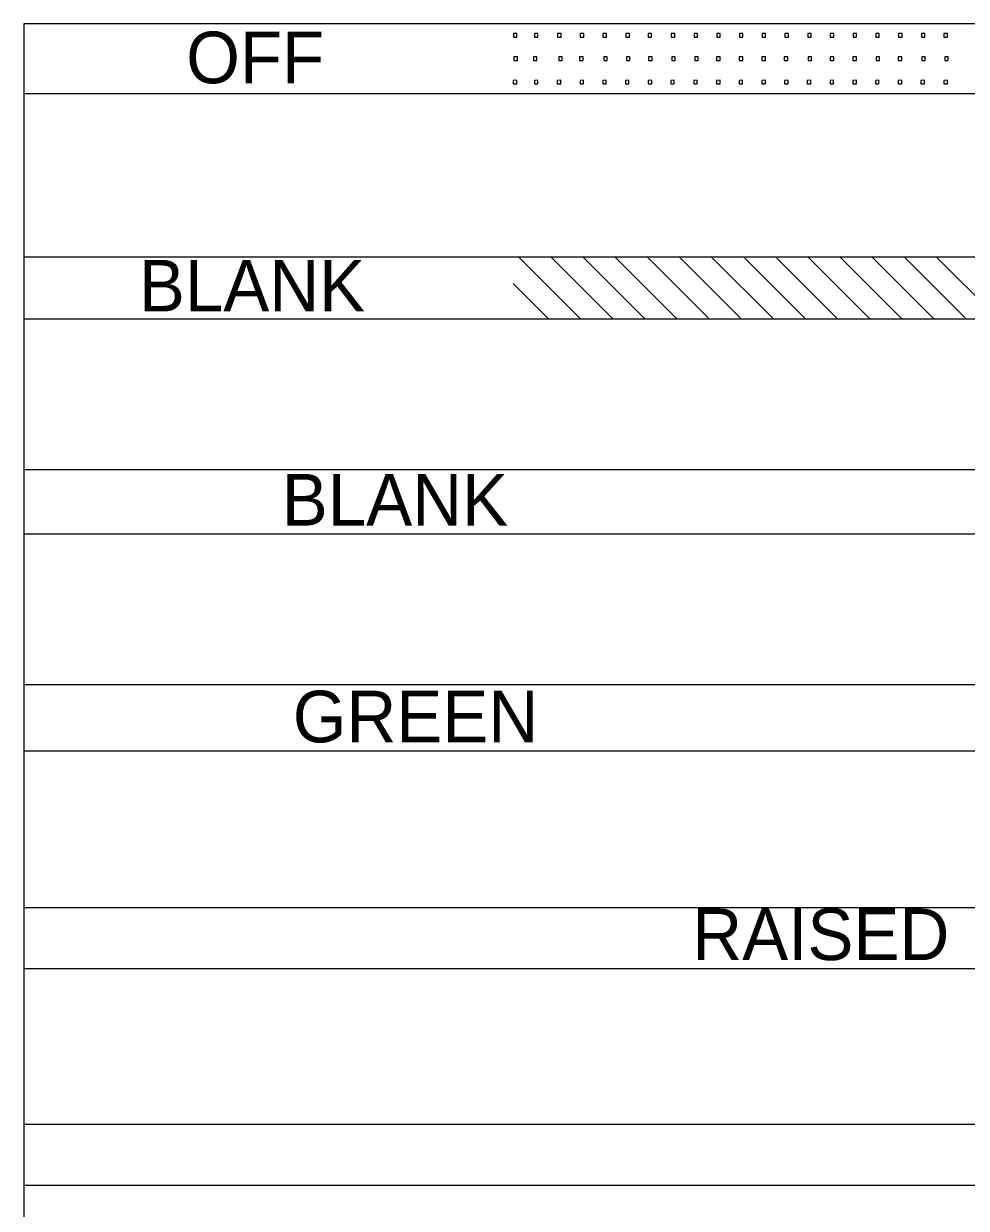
# Model space of a CAD drawing. Extents: x 15 to 764, y 7 to 487.
# Drawn here: x 462.7 to 526.6, y 103.6 to 184 of the extents above; entities that cross this region are included whole.
import ezdxf

# ---------------------------------------------------------------- set-up
doc = ezdxf.new("R2010")
doc.units = 0
doc.layers.add('Default', color=7, linetype='Continuous')
doc.layers.add('TextStructures', color=7, linetype='Continuous')

msp = doc.modelspace()

# ---------------------------------------------------------------- linework, layer by layer
at = {"layer": 'Default'}
for p, q in [((756.61, 183.984), (462.687, 183.984)), ((462.687, 183.984), (462.687, 47.445)), ((462.687, 179.246), (756.61, 179.246)), ((462.687, 168.178), (756.61, 168.178)), ((496.242, 168.178), (500.448, 163.965)), ((498.42, 168.178), (502.627, 163.965)), ((500.599, 168.178), (504.805, 163.965)), ((502.777, 168.178), (506.984, 163.965)), ((504.956, 168.178), (509.162, 163.965)), ((507.134, 168.178), (511.341, 163.965)), ((509.313, 168.178), (513.519, 163.965)), ((511.491, 168.178), (515.698, 163.965)), ((513.669, 168.178), (517.876, 163.965)), ((515.848, 168.178), (520.055, 163.965)), ((518.026, 168.178), (522.233, 163.965)), ((520.205, 168.178), (524.412, 163.965)), ((522.383, 168.178), (526.59, 163.965)), ((524.562, 168.178), (528.769, 163.965)), ((495.877, 166.361), (498.27, 163.965)), ((462.687, 163.965), (756.61, 163.965)), ((462.687, 153.744), (756.61, 153.744)), ((462.687, 149.383), (756.61, 149.383)), ((462.687, 139.163), (756.61, 139.163)), ((462.687, 134.675), (756.61, 134.675)), ((462.687, 124.052), (756.61, 124.052)), ((462.687, 119.905), (756.61, 119.905)), ((462.687, 109.343), (756.61, 109.343))]:
    msp.add_line(p, q, dxfattribs=at)
for points in [[(496.133, 183.08), (496.133, 183.319), (495.897, 183.318), (495.897, 183.08), (496.133, 183.08)], [(497.559, 183.08), (497.559, 183.319), (497.322, 183.318), (497.322, 183.08), (497.559, 183.08)], [(499.122, 183.08), (499.122, 183.319), (498.886, 183.318), (498.886, 183.08), (499.122, 183.08)], [(500.668, 183.08), (500.668, 183.319), (500.431, 183.318), (500.431, 183.08), (500.668, 183.08)], [(502.195, 183.08), (502.195, 183.319), (501.959, 183.318), (501.959, 183.08), (502.195, 183.08)], [(503.759, 183.08), (503.759, 183.319), (503.523, 183.318), (503.523, 183.08), (503.759, 183.08)], [(505.268, 183.08), (505.268, 183.319), (505.032, 183.318), (505.032, 183.08), (505.268, 183.08)], [(506.832, 183.08), (506.832, 183.319), (506.595, 183.318), (506.595, 183.08), (506.832, 183.08)], [(508.378, 183.08), (508.378, 183.319), (508.141, 183.318), (508.141, 183.08), (508.378, 183.08)], [(509.923, 183.08), (509.923, 183.319), (509.687, 183.318), (509.687, 183.08), (509.923, 183.08)], [(511.451, 183.08), (511.451, 183.319), (511.214, 183.318), (511.214, 183.08), (511.451, 183.08)], [(512.996, 183.08), (512.996, 183.319), (512.76, 183.318), (512.76, 183.08), (512.996, 183.08)], [(514.542, 183.08), (514.542, 183.319), (514.305, 183.318), (514.305, 183.08), (514.542, 183.08)], [(516.087, 183.08), (516.087, 183.319), (515.851, 183.318), (515.851, 183.08), (516.087, 183.08)], [(517.615, 183.08), (517.615, 183.319), (517.378, 183.318), (517.378, 183.08), (517.615, 183.08)], [(519.16, 183.08), (519.16, 183.319), (518.924, 183.318), (518.924, 183.08), (519.16, 183.08)], [(520.706, 183.08), (520.706, 183.319), (520.469, 183.318), (520.469, 183.08), (520.706, 183.08)], [(522.251, 183.08), (522.251, 183.319), (522.015, 183.318), (522.015, 183.08), (522.251, 183.08)], [(523.797, 183.08), (523.797, 183.319), (523.56, 183.318), (523.56, 183.08), (523.797, 183.08)], [(525.324, 183.08), (525.324, 183.319), (525.088, 183.318), (525.088, 183.08), (525.324, 183.08)], [(496.161, 181.491), (496.161, 181.73), (495.924, 181.729), (495.924, 181.491), (496.161, 181.491)], [(497.489, 181.491), (497.489, 181.73), (497.252, 181.729), (497.252, 181.491), (497.489, 181.491)], [(499.207, 181.491), (499.207, 181.73), (498.971, 181.729), (498.971, 181.491), (499.207, 181.491)], [(500.613, 181.491), (500.613, 181.73), (500.377, 181.729), (500.377, 181.491), (500.613, 181.491)], [(502.254, 181.491), (502.254, 181.73), (502.017, 181.729), (502.017, 181.491), (502.254, 181.491)], [(503.79, 181.491), (503.79, 181.73), (503.554, 181.729), (503.554, 181.491), (503.79, 181.491)], [(505.301, 181.491), (505.301, 181.73), (505.064, 181.729), (505.064, 181.491), (505.301, 181.491)], [(506.863, 181.491), (506.863, 181.73), (506.627, 181.729), (506.627, 181.491), (506.863, 181.491)], [(508.426, 181.491), (508.426, 181.73), (508.189, 181.729), (508.189, 181.491), (508.426, 181.491)], [(509.91, 181.491), (509.91, 181.73), (509.673, 181.729), (509.673, 181.491), (509.91, 181.491)], [(511.446, 181.491), (511.446, 181.73), (511.21, 181.729), (511.21, 181.491), (511.446, 181.491)], [(512.983, 181.491), (512.983, 181.73), (512.746, 181.729), (512.746, 181.491), (512.983, 181.491)], [(514.493, 181.491), (514.493, 181.73), (514.257, 181.729), (514.257, 181.491), (514.493, 181.491)], [(516.108, 181.491), (516.108, 181.73), (515.871, 181.729), (515.871, 181.491), (516.108, 181.491)], [(517.618, 181.491), (517.618, 181.73), (517.381, 181.729), (517.381, 181.491), (517.618, 181.491)], [(519.155, 181.491), (519.155, 181.73), (518.918, 181.729), (518.918, 181.491), (519.155, 181.491)], [(520.717, 181.491), (520.717, 181.73), (520.48, 181.729), (520.48, 181.491), (520.717, 181.491)], [(522.227, 181.491), (522.227, 181.73), (521.991, 181.729), (521.991, 181.491), (522.227, 181.491)], [(523.816, 181.491), (523.816, 181.73), (523.579, 181.729), (523.579, 181.491), (523.816, 181.491)], [(525.378, 181.491), (525.378, 181.73), (525.142, 181.729), (525.142, 181.491), (525.378, 181.491)], [(496.122, 179.904), (496.122, 180.143), (495.886, 180.142), (495.886, 179.904), (496.122, 179.904)], [(497.557, 179.904), (497.557, 180.143), (497.32, 180.142), (497.32, 179.904), (497.557, 179.904)], [(499.101, 179.904), (499.101, 180.143), (498.864, 180.142), (498.864, 179.904), (499.101, 179.904)], [(500.645, 179.904), (500.645, 180.143), (500.409, 180.142), (500.409, 179.904), (500.645, 179.904)], [(502.19, 179.904), (502.19, 180.143), (501.953, 180.142), (501.953, 179.904), (502.19, 179.904)], [(503.725, 179.904), (503.725, 180.143), (503.488, 180.142), (503.488, 179.904), (503.725, 179.904)], [(505.269, 179.904), (505.269, 180.143), (505.033, 180.142), (505.033, 179.904), (505.269, 179.904)], [(506.804, 179.904), (506.804, 180.143), (506.568, 180.142), (506.568, 179.904), (506.804, 179.904)], [(508.358, 179.904), (508.358, 180.143), (508.121, 180.142), (508.121, 179.904), (508.358, 179.904)], [(509.902, 179.904), (509.902, 180.143), (509.665, 180.142), (509.665, 179.904), (509.902, 179.904)], [(511.437, 179.904), (511.437, 180.143), (511.201, 180.142), (511.201, 179.904), (511.437, 179.904)], [(512.982, 179.904), (512.982, 180.143), (512.745, 180.142), (512.745, 179.904), (512.982, 179.904)], [(514.517, 179.904), (514.517, 180.143), (514.28, 180.142), (514.28, 179.904), (514.517, 179.904)], [(516.052, 179.904), (516.052, 180.143), (515.815, 180.142), (515.815, 179.904), (516.052, 179.904)], [(517.605, 179.904), (517.605, 180.143), (517.369, 180.142), (517.369, 179.904), (517.605, 179.904)], [(519.15, 179.904), (519.15, 180.143), (518.913, 180.142), (518.913, 179.904), (519.15, 179.904)], [(520.676, 179.904), (520.676, 180.143), (520.439, 180.142), (520.439, 179.904), (520.676, 179.904)], [(522.229, 179.904), (522.229, 180.143), (521.992, 180.142), (521.992, 179.904), (522.229, 179.904)], [(523.764, 179.904), (523.764, 180.143), (523.528, 180.142), (523.528, 179.904), (523.764, 179.904)], [(525.318, 179.904), (525.318, 180.143), (525.081, 180.142), (525.081, 179.904), (525.318, 179.904)]]:
    msp.add_lwpolyline(points, dxfattribs=at)
at = {"layer": 'TextStructures'}
msp.add_line((462.687, 105.216), (756.61, 105.216), dxfattribs=at)

# ---------------------------------------------------------------- texts
for s, p in [('OFF', (473.707, 179.944)), ('BLANK', (470.495, 164.465)), ('BLANK', (480.184, 149.946)), ('GREEN', (480.935, 135.245)), ('RAISED', (508.027, 120.475))]:
    msp.add_text(s, height=3.5, rotation=0.00072, dxfattribs=at).set_placement(p)

doc.saveas('drawing.dxf')
